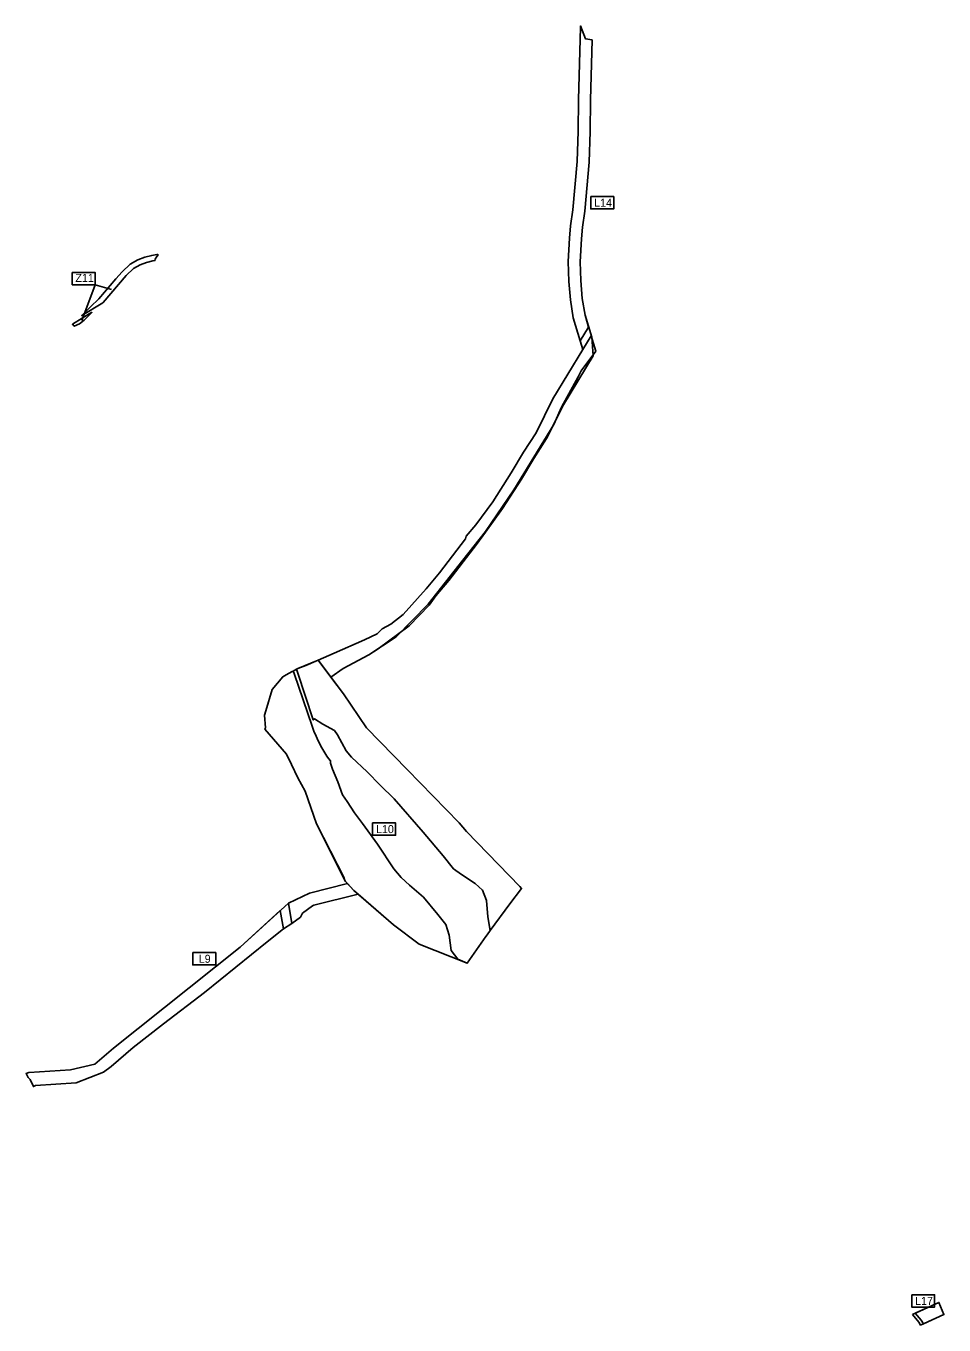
# Model space of a CAD drawing. Extents: x -547623 to -530360, y -1095798 to -1086523.
# Drawn here: x -540180 to -539033, y -1093183 to -1091559 of the extents above; entities that cross this region are included whole.
import ezdxf

# ---------------------------------------------------------------- set-up
doc = ezdxf.new("R2010")
doc.units = 0
for name, color, linetype in [('Vrstva 32', 7, 'Continuous'), ('Vrstva 33', 7, 'Continuous'), ('Vrstva 36', 7, 'Continuous'), ('Vrstva 43', 7, 'Continuous'), ('Vrstva 59', 7, 'Continuous'), ('Vrstva 73', 7, 'Continuous')]:
    doc.layers.add(name, color=color, linetype=linetype)

msp = doc.modelspace()

# ---------------------------------------------------------------- linework, layer by layer
at = {"layer": 'Vrstva 32'}
msp.add_line((-539831.1, -1092515.4), (-539816.8, -1092556.3), dxfattribs=at)
for points in [[(-539816.8, -1092556.3), (-539780.8, -1092628.4), (-539770.1, -1092639.4), (-539720.7, -1092682.4), (-539688.7, -1092706.6), (-539628.9, -1092730.5), (-539605.3, -1092697.2), (-539603.6, -1092694.8), (-539599.8, -1092689.4), (-539575.6, -1092656.1), (-539560.8, -1092637), (-539563.1, -1092634.6), (-539629.6, -1092566), (-539638.7, -1092555.2), (-539703.5, -1092488.3), (-539754.5, -1092436.3), (-539783.3, -1092393.8), (-539814.8, -1092351.8), (-539840.1, -1092362.3)], [(-539854.9, -1092370.1), (-539859, -1092372.4), (-539872.2, -1092388.6), (-539880.2, -1092415.1), (-539881.9, -1092420.7), (-539880.7, -1092436.4), (-539881.3, -1092438)], [(-539840.1, -1092362.3), (-539841.9, -1092363.2), (-539845.9, -1092365.3), (-539847.1, -1092365.9), (-539854.9, -1092370.1)], [(-539881.3, -1092438), (-539854.2, -1092469.1)], [(-539854.2, -1092469.1), (-539848.2, -1092482.1), (-539840.3, -1092498.7), (-539831.1, -1092515.4)]]:
    msp.add_lwpolyline(points, dxfattribs=at)
at = {"layer": 'Vrstva 33'}
for points in [[(-539472.6, -1091576.7), (-539474.5, -1091651.8), (-539475.1, -1091691.2), (-539476.4, -1091729.6), (-539481.7, -1091790.7), (-539484.8, -1091810.5), (-539485.9, -1091825.3), (-539487.5, -1091853.9), (-539486.8, -1091877.5), (-539484.9, -1091899.7), (-539481.5, -1091920.5), (-539473.1, -1091948.3), (-539471.4, -1091971.3), (-539508.5, -1092032.5), (-539529.6, -1092074.8), (-539545.4, -1092099.8), (-539561, -1092125.4), (-539584.4, -1092162.4), (-539605.9, -1092191.8), (-539617.1, -1092207.1), (-539651.8, -1092252.1), (-539667.8, -1092271.2), (-539676.2, -1092283.1), (-539701.2, -1092309), (-539739.9, -1092337.4), (-539751.5, -1092345.3), (-539783.7, -1092362.3), (-539798.9, -1092372.9), (-539814.8, -1092351.8), (-539794.7, -1092343.1), (-539756.9, -1092326.3), (-539741, -1092318.8), (-539734.8, -1092312.7), (-539724, -1092306.6), (-539708.5, -1092294.5), (-539680.1, -1092262.5), (-539663.2, -1092242.5), (-539630.8, -1092200.2), (-539629.8, -1092196.8), (-539617.7, -1092182.5), (-539596.8, -1092154), (-539573.8, -1092117.5), (-539558.2, -1092091.8), (-539542.7, -1092067.5), (-539521.6, -1092025.2), (-539484.2, -1091963.5), (-539487.5, -1091952.6), (-539496.2, -1091923.8), (-539499.8, -1091901.5), (-539501.8, -1091878.4), (-539502.5, -1091853.7), (-539500.9, -1091824.3), (-539499.8, -1091808.8), (-539496.6, -1091788.9), (-539491.3, -1091728.7), (-539490.1, -1091690.8), (-539489.5, -1091651.4), (-539487.2, -1091560.6), (-539487.2, -1091559.2), (-539481, -1091575.3), (-539472.6, -1091576.7)], [(-539834.4, -1092668.1), (-539836.9, -1092672.9), (-539847.7, -1092680.9), (-539858, -1092687.7), (-539878.4, -1092703.7), (-539956.7, -1092767.2), (-540007.8, -1092806.4), (-540045.8, -1092835.7), (-540073.2, -1092859.5), (-540082.8, -1092866.7), (-540117.2, -1092880.1), (-540167.8, -1092883.1), (-540168.7, -1092883.6), (-540170.5, -1092884.6), (-540174.7, -1092875.9), (-540177.1, -1092873.1), (-540179.7, -1092868.4), (-540176.1, -1092867.2), (-540175.7, -1092867.1), (-540124.2, -1092863.8), (-540093.8, -1092856.7), (-540070.6, -1092836.6), (-539912.2, -1092710.4), (-539851.9, -1092655.5), (-539825.8, -1092643), (-539778.3, -1092631)], [(-539778.3, -1092631), (-539770.1, -1092639.4), (-539764.8, -1092644), (-539820.4, -1092658.1), (-539822.1, -1092658.9)], [(-539822.1, -1092658.9), (-539834.4, -1092668.1)], [(-539072.7, -1093169.4), (-539039.5, -1093154.4), (-539033.2, -1093169.6), (-539062.4, -1093182.6), (-539064.8, -1093179.1), (-539072.7, -1093169.4)]]:
    msp.add_lwpolyline(points, dxfattribs=at)
at = {"layer": 'Vrstva 36'}
for points in [[(-539474.3, -1091772.4), (-539445.7, -1091772.4), (-539445.7, -1091787.9), (-539474.3, -1091787.9)], [(-539746.8, -1092555.1), (-539718.2, -1092555.1), (-539718.2, -1092570.6), (-539746.8, -1092570.6)], [(-539971.5, -1092717.1), (-539942.8, -1092717.1), (-539942.8, -1092732.6), (-539971.5, -1092732.6)], [(-539073.5, -1093144.7), (-539044.9, -1093144.7), (-539044.9, -1093160.2), (-539073.5, -1093160.2)]]:
    msp.add_lwpolyline(points, close=True, dxfattribs=at)
at = {"layer": 'Vrstva 43'}
for points in [[(-540067.4, -1091875.3), (-540088.6, -1091900.1), (-540099, -1091910.3), (-540101.6, -1091912.8), (-540110, -1091921.2), (-540083.9, -1091905.3), (-540083.5, -1091904.9), (-540054.6, -1091871.2), (-540045.6, -1091862.5), (-540037.1, -1091857.8), (-540029.3, -1091854.7), (-540021.4, -1091852.8), (-540018.8, -1091852.4), (-540018.3, -1091850.7), (-540016.3, -1091847.5)], [(-540016.3, -1091845), (-540022.7, -1091845.9), (-540031.4, -1091848.1), (-540040.1, -1091851.5), (-540049.8, -1091856.8), (-540059.7, -1091866.4), (-540067.4, -1091875.3)], [(-540016.3, -1091847.5), (-540014.7, -1091845.1), (-540015.5, -1091844.9), (-540016.3, -1091845)], [(-540097.3, -1091917), (-540121.7, -1091931.9), (-540119.4, -1091934.4), (-540113.1, -1091931.5), (-540107, -1091926.7), (-540097.4, -1091917.1), (-540097.3, -1091917)]]:
    msp.add_lwpolyline(points, dxfattribs=at)
at = {"layer": 'Vrstva 59'}
for q in [(-540110.1, -1091927.1), (-540073, -1091888.4)]:
    msp.add_line((-540093.4, -1091882.6), q, dxfattribs=at)
msp.add_lwpolyline([(-540122, -1091867.1), (-540093.4, -1091867.1), (-540093.4, -1091882.6), (-540122, -1091882.6)], close=True, dxfattribs=at)
at = {"layer": 'Vrstva 73'}
for points in [[(-539487.5, -1091952.6), (-539477, -1091935.6), (-539481.5, -1091920.5), (-539484.9, -1091899.7), (-539486.8, -1091877.5), (-539487.5, -1091853.9), (-539485.9, -1091825.3), (-539484.8, -1091810.5), (-539481.7, -1091790.7), (-539476.4, -1091729.6), (-539475.1, -1091691.2), (-539474.5, -1091651.8), (-539472.6, -1091576.7), (-539481, -1091575.3), (-539487.2, -1091559.2), (-539487.2, -1091560.6), (-539489.5, -1091651.4), (-539490.1, -1091690.8), (-539491.3, -1091728.7), (-539496.6, -1091788.9), (-539499.8, -1091808.8), (-539500.9, -1091824.3), (-539502.5, -1091853.7), (-539501.8, -1091878.4), (-539499.8, -1091901.5), (-539496.2, -1091923.8), (-539487.5, -1091952.6)], [(-539486.3, -1091990.1), (-539467.9, -1091965.7), (-539473.8, -1091946.3), (-539484.2, -1091963.5), (-539521.6, -1092025.2), (-539542.7, -1092067.5), (-539558.2, -1092091.8), (-539573.8, -1092117.5), (-539596.8, -1092154), (-539617.7, -1092182.5), (-539629.8, -1092196.8), (-539630.8, -1092200.2), (-539663.2, -1092242.5), (-539680.1, -1092262.5), (-539708.5, -1092294.5), (-539724, -1092306.6), (-539734.8, -1092312.7), (-539741, -1092318.8), (-539756.9, -1092326.3), (-539794.7, -1092343.1), (-539814.8, -1092351.8), (-539798.9, -1092372.9), (-539783.7, -1092362.3), (-539751.5, -1092345.3), (-539717.6, -1092322.4), (-539677.6, -1092281.8), (-539634.1, -1092226.9), (-539605.7, -1092190.9), (-539570.6, -1092138.8), (-539520.4, -1092057.4), (-539511, -1092035.6), (-539490.1, -1091997.7), (-539486.3, -1091990.1)], [(-539783.3, -1092393.8), (-539798.9, -1092372.9), (-539814.8, -1092351.8), (-539830.4, -1092358.3), (-539840.1, -1092362.3), (-539841.9, -1092363.2), (-539840.6, -1092366.7), (-539820.9, -1092426.4), (-539819.3, -1092425.1), (-539809, -1092431.6), (-539794.5, -1092439.8), (-539790.6, -1092444.9), (-539780, -1092465), (-539773.3, -1092473.1), (-539753.8, -1092491.1), (-539737.2, -1092507.9), (-539720.1, -1092525), (-539683.6, -1092566.7), (-539658.7, -1092596.1), (-539645.7, -1092612.5), (-539635.6, -1092619.6), (-539618.9, -1092630.7), (-539609.6, -1092639.3), (-539604.4, -1092652.3), (-539602.9, -1092672.4), (-539599.8, -1092689.4), (-539575.6, -1092656.1), (-539560.8, -1092637), (-539563.1, -1092634.6), (-539629.6, -1092566), (-539638.7, -1092555.2), (-539703.5, -1092488.3), (-539754.5, -1092436.3), (-539783.3, -1092393.8)], [(-539872.2, -1092388.6), (-539880.2, -1092415.1), (-539881.9, -1092420.7), (-539880.7, -1092436.4), (-539881.3, -1092438), (-539854.2, -1092469.1), (-539848.2, -1092482.1), (-539840.3, -1092498.7), (-539831.1, -1092515.4), (-539816.8, -1092556.3), (-539782, -1092624.7), (-539782.6, -1092624.8), (-539780.8, -1092628.4), (-539778.3, -1092631), (-539770.1, -1092639.4), (-539764.8, -1092644), (-539720.7, -1092682.4), (-539688.7, -1092706.6), (-539628.9, -1092730.5), (-539640.5, -1092725.3), (-539648.7, -1092714.5), (-539651.3, -1092695.5), (-539655.4, -1092682.1), (-539665.4, -1092669.5), (-539683.3, -1092647.9), (-539700.8, -1092633), (-539711.2, -1092623.3), (-539720.5, -1092612.5), (-539740.6, -1092581.6), (-539759.5, -1092555.9), (-539769.4, -1092542.5), (-539778.7, -1092528.4), (-539784.3, -1092520), (-539790.4, -1092503.8), (-539797.1, -1092487.8), (-539799.5, -1092480.5), (-539799.5, -1092477.5), (-539802.1, -1092474.5), (-539803.8, -1092471.7), (-539810.1, -1092461.4), (-539814.8, -1092452.7), (-539818.7, -1092444), (-539819.9, -1092441.9), (-539822.4, -1092434.2), (-539844.9, -1092368.3), (-539845.9, -1092365.3), (-539847.1, -1092365.9), (-539854.9, -1092370.1), (-539859, -1092372.4), (-539872.2, -1092388.6)], [(-539770.1, -1092639.4), (-539778.3, -1092631), (-539825.8, -1092643), (-539851.9, -1092655.5), (-539847.7, -1092680.9), (-539836.9, -1092672.9), (-539834.4, -1092668.1), (-539822.1, -1092658.9), (-539820.4, -1092658.1), (-539764.8, -1092644), (-539770.1, -1092639.4)], [(-539858, -1092687.7), (-539862.1, -1092664.7), (-539912.2, -1092710.4), (-540070.6, -1092836.6), (-540093.8, -1092856.7), (-540124.2, -1092863.8), (-540175.7, -1092867.1), (-540176.1, -1092867.2), (-540179.7, -1092868.4), (-540177.1, -1092873.1), (-540174.7, -1092875.9), (-540170.5, -1092884.6), (-540168.7, -1092883.6), (-540167.8, -1092883.1), (-540117.2, -1092880.1), (-540082.8, -1092866.7), (-540073.2, -1092859.5), (-540045.8, -1092835.7), (-540007.8, -1092806.4), (-539956.7, -1092767.2), (-539878.4, -1092703.7), (-539858, -1092687.7)], [(-539061.7, -1093176.7), (-539058.9, -1093181), (-539033.2, -1093169.6), (-539039.5, -1093154.4), (-539069, -1093167.7), (-539061.7, -1093176.7)]]:
    msp.add_lwpolyline(points, dxfattribs=at)

# ---------------------------------------------------------------- texts
at = {"layer": 'Vrstva 36'}
for s, p in [('L14', (-539470.1, -1091785.1)), ('L10', (-539742.6, -1092567.9)), ('L9', (-539964, -1092729.9)), ('L17', (-539069.3, -1093157.5))]:
    msp.add_text(s, height=10, dxfattribs=at).set_placement(p)
at = {"layer": 'Vrstva 59'}
msp.add_text('Z11', height=10, dxfattribs=at).set_placement((-540118.1, -1091879.1))

doc.saveas('drawing.dxf')
